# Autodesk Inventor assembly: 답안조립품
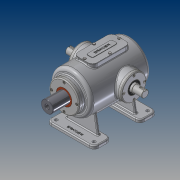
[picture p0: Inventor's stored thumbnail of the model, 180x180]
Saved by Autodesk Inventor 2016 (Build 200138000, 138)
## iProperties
Created: 2016-06
Part Number: 답안조립품
Document SubType Name: Assembly
Designer: sys
Author: sys
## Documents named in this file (15)
- C:\Users\user\Desktop\Manufacturing1급_신용성\공용부품\답안조립품.iam
- C:\Users\user\Desktop\Manufacturing1급_신용성\공용부품\1.본체.ipt
- C:\Users\user\Desktop\Manufacturing1급_신용성\공용부품\2.베어링 6205.ipt
- 베어링 6205.ipt
- C:\Users\user\Desktop\Manufacturing1급_신용성\공용부품\8.편심축-[구동부].ipt
- C:\Users\user\Desktop\Manufacturing1급_신용성\공용부품\5.슬라이드 커버.ipt
- C:\Users\user\Desktop\Manufacturing1급_신용성\공용부품\6.부시.ipt
- C:\Users\user\Desktop\Manufacturing1급_신용성\공용부품\7.슬라이드.ipt
- C:\Users\user\Desktop\Manufacturing1급_신용성\공용부품\12.가변스프링.ipt
- C:\Users\user\Desktop\Manufacturing1급_신용성\공용부품\3.축 커버.ipt
- C:\Users\user\Desktop\Manufacturing1급_신용성\공용부품\4.오일실.ipt
- 오일실.ipt
- C:\Users\user\Desktop\Manufacturing1급_신용성\공용부품\11.볼트 M4x0.7.ipt
- C:\Users\user\Desktop\Manufacturing1급_신용성\공용부품\9.상부커버.ipt
- C:\Users\user\Desktop\Manufacturing1급_신용성\공용부품\10.육각머리볼트 M4.ipt
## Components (25 placed, 10 different names)
1. 1.본체:1 — 각도:3
2. 8.편심축-[구동부]:1 — 각도:3
3. 5.슬라이드 커버:1
4. 6.부시:1 — 각도:1
5. 7.슬라이드:1 — 각도:2
6. 12.가변스프링:1
7. 3.축 커버:1
8. 3.축 커버:2
9. 9.상부커버:1
10. 10.육각머리볼트 M4:1
11. 10.육각머리볼트 M4:2
12. 10.육각머리볼트 M4:3
13. 10.육각머리볼트 M4:4
14. M4x0.7:1
15. M4x0.7:4
16. M4x0.7:5
17. M4x0.7:6
18. M4x0.7:2
19. M4x0.7:7
20. M4x0.7:8
21. M4x0.7:9
22. M4x0.7:3 — 각도:1, 각도:2
23. M4x0.7:10
24. M4x0.7:11
25. M4x0.7:12
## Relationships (3: Angle 3)
- 각도:1 [Angle]: 6.부시:1 ↔ M4x0.7:3
- 각도:2 [Angle]: 7.슬라이드:1 ↔ M4x0.7:3
- 각도:3 [Angle]: 1.본체:1 ↔ 8.편심축-[구동부]:1
